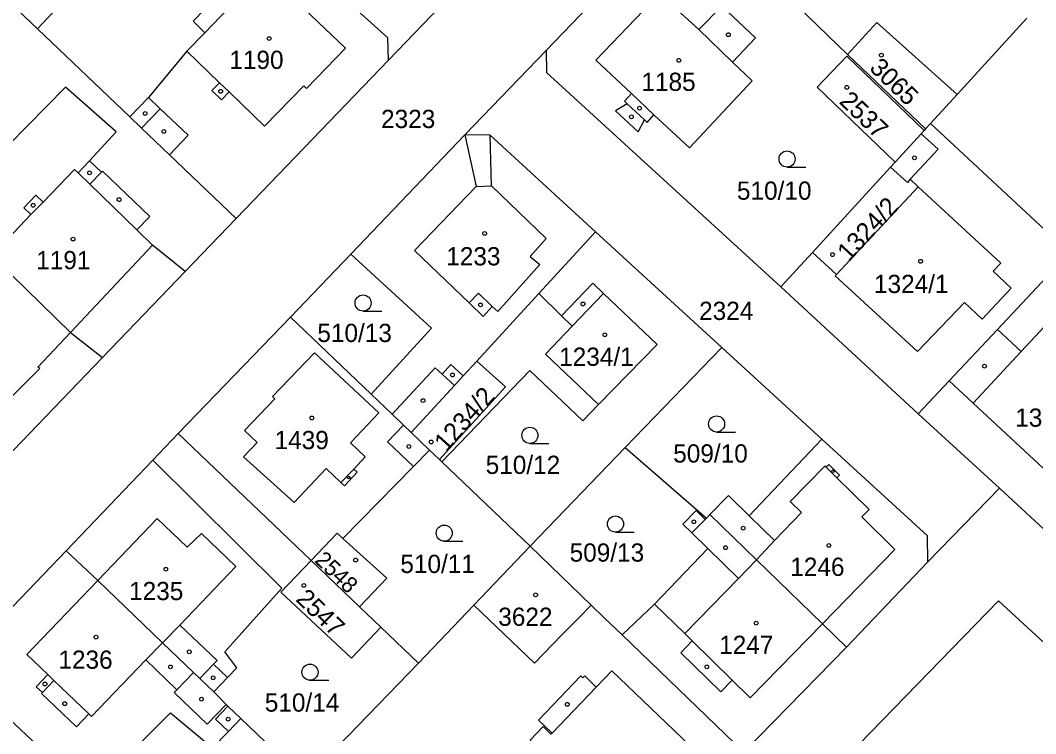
# Model space of a CAD drawing. Extents: x -679220 to -673243, y -1075091 to -1066557.
# Drawn here: x -675883.3 to -675788.6, y -1072056.6 to -1071990 of the extents above; entities that cross this region are included whole.
import ezdxf

# ---------------------------------------------------------------- set-up
doc = ezdxf.new("R2010")
doc.units = 0
for name, color, linetype in [('Hranice parcel', 7, 'Continuous'), ('Parcelní čísla', 7, 'Continuous'), ('Vnitřní kresba', 7, 'Continuous'), ('Značky budov', 7, 'Continuous'), ('Značky kultur', 7, 'Continuous')]:
    doc.layers.add(name, color=color, linetype=linetype)

msp = doc.modelspace()

# ---------------------------------------------------------------- linework, layer by layer
at = {"layer": 'Hranice parcel'}
for p, q in [((-675881.66, -1071990.83), (-675867.2, -1071975.24)), ((-675820.87, -1071978.95), (-675834.25, -1071992.83)), ((-675820.87, -1071978.95), (-675806.12, -1071993.2)), ((-675890.64, -1071982.25), (-675881.66, -1071990.83)), ((-675848.93, -1071993.73), (-675841.54, -1071986.02)), ((-675789.4, -1071989.83), (-675795.92, -1071996.95)), ((-675881.66, -1071990.83), (-675873.06, -1071999.04)), ((-675841.83, -1072000.7), (-675834.25, -1071992.83)), ((-675863.14, -1072008.51), (-675848.93, -1071993.73)), ((-675806.12, -1071993.2), (-675798.85, -1072000.15)), ((-675798.4, -1071999.65), (-675795.92, -1071996.95)), ((-675799, -1072000.3), (-675799.27, -1072000.6)), ((-675798.85, -1072000.15), (-675799, -1072000.3)), ((-675798.4, -1071999.65), (-675798.85, -1072000.15)), ((-675785.46, -1072011.69), (-675798.4, -1071999.65)), ((-675841.83, -1072000.7), (-675852.46, -1072011.83)), ((-675799.27, -1072000.6), (-675801.69, -1072003.25)), ((-675867.89, -1072013.44), (-675863.14, -1072008.51)), ((-675834.92, -1072015.5), (-675829.63, -1072009.75)), ((-675817.86, -1072020.54), (-675829.63, -1072009.75)), ((-675852.46, -1072011.83), (-675858.09, -1072017.72)), ((-675809.41, -1072011.67), (-675812.34, -1072014.87)), ((-675875.62, -1072021.48), (-675867.89, -1072013.44)), ((-675840.71, -1072021.8), (-675834.92, -1072015.5)), ((-675812.34, -1072014.87), (-675799.53, -1072026.71)), ((-675858.09, -1072017.72), (-675868.54, -1072028.55)), ((-675850.57, -1072024.9), (-675858.09, -1072017.72)), ((-675817.86, -1072020.54), (-675826.86, -1072029.88)), ((-675808.52, -1072029.09), (-675817.86, -1072020.54)), ((-675884.7, -1072030.92), (-675875.62, -1072021.48)), ((-675799.53, -1072026.71), (-675791.97, -1072033.67)), ((-675868.54, -1072028.55), (-675870.92, -1072031.05)), ((-675856.15, -1072040.41), (-675868.54, -1072028.55)), ((-675846.83, -1072028.46), (-675845.12, -1072030.1)), ((-675826.86, -1072029.88), (-675835.72, -1072039.08)), ((-675826.86, -1072029.88), (-675819.29, -1072036.44)), ((-675845.12, -1072030.1), (-675844.17, -1072030.98)), ((-675870.92, -1072031.05), (-675878.99, -1072039.49)), ((-675844.17, -1072030.98), (-675843.97, -1072031.2)), ((-675835.72, -1072039.08), (-675843.97, -1072031.2)), ((-675791.97, -1072033.67), (-675798.63, -1072040.54)), ((-675791.97, -1072033.67), (-675786.57, -1072038.64)), ((-675818.97, -1072036.12), (-675819.29, -1072036.44)), ((-675840.97, -1072044.56), (-675835.72, -1072039.08)), ((-675835.72, -1072039.08), (-675830.03, -1072044.56)), ((-675878.99, -1072039.49), (-675889.45, -1072050.36)), ((-675851.64, -1072044.73), (-675856.15, -1072040.41)), ((-675806.24, -1072048.49), (-675798.63, -1072040.54)), ((-675849.65, -1072046.63), (-675851.64, -1072044.73)), ((-675840.97, -1072044.56), (-675846.15, -1072049.98)), ((-675846.15, -1072049.98), (-675849.65, -1072046.63)), ((-675827.14, -1072047.35), (-675815.81, -1072058.29)), ((-675815.81, -1072058.29), (-675806.24, -1072048.49)), ((-675889.45, -1072050.36), (-675878, -1072061.1)), ((-675856.72, -1072060.87), (-675846.15, -1072049.98)), ((-675862.71, -1072055.13), (-675856.72, -1072060.87))]:
    msp.add_line(p, q, dxfattribs=at)
for points in [[(-675858.37, -1071983.2), (-675860.31, -1071985.21), (-675863.53, -1071988.54), (-675864.44, -1071987.66), (-675864.81, -1071988.05), (-675865, -1071987.87), (-675867.17, -1071990.12), (-675866.07, -1071991.18), (-675867.74, -1071992.91), (-675871.32, -1071997.22), (-675873.06, -1071999.04)], [(-675848.93, -1071993.73), (-675849.01, -1071991.65), (-675858.37, -1071983.2)], [(-675826.28, -1071996.85), (-675826.93, -1071997.58), (-675826.68, -1071997.8), (-675827.77, -1071998.48), (-675825.66, -1072000.44), (-675825.06, -1071999.32), (-675824.82, -1071999.54), (-675824.2, -1071998.83), (-675820.87, -1072001.92), (-675815.03, -1071995.66), (-675816.85, -1071993.94), (-675814.7, -1071991.66), (-675817.85, -1071988.7), (-675820, -1071990.89), (-675823.68, -1071987.53), (-675829.61, -1071993.73), (-675826.28, -1071996.85)], [(-675795.92, -1071996.95), (-675803.41, -1071990.22), (-675806.12, -1071993.2)], [(-675834.25, -1071992.83), (-675834.22, -1071994.88), (-675812.34, -1072014.87)], [(-675799, -1072000.3), (-675806.19, -1071993.38), (-675808.95, -1071996.26), (-675801.69, -1072003.25)], [(-675867.89, -1072013.44), (-675870.94, -1072010.99), (-675872.41, -1072009.58), (-675871.2, -1072008.33), (-675875.6, -1072004.09), (-675875.71, -1072004.2), (-675876.81, -1072003.14), (-675874.33, -1072000.43), (-675879.05, -1071996.27), (-675886.17, -1072003.47), (-675888.43, -1072001.12), (-675890.47, -1072003.13), (-675892.63, -1072005.27)], [(-675873.06, -1071999.04), (-675871.96, -1072000.09), (-675869.36, -1072002.57), (-675863.14, -1072008.51)], [(-675829.63, -1072009.75), (-675839.47, -1072000.75), (-675841.83, -1072000.7)], [(-675799.27, -1072000.6), (-675797.69, -1072002.05), (-675800.28, -1072004.85), (-675799.54, -1072005.54), (-675807.16, -1072013.74), (-675809.41, -1072011.67)], [(-675801.69, -1072003.25), (-675802.12, -1072003.71), (-675809.41, -1072011.67)], [(-675892.63, -1072005.27), (-675887.79, -1072010.13), (-675885.95, -1072011.97), (-675885.52, -1072012.38), (-675878.61, -1072019.15), (-675875.62, -1072021.48)], [(-675852.46, -1072011.83), (-675844.93, -1072018.75), (-675850.57, -1072024.9)], [(-675786.65, -1072012.97), (-675792.16, -1072018.85), (-675796.66, -1072023.65), (-675799.53, -1072026.71)], [(-675843.97, -1072031.2), (-675835.75, -1072022.67), (-675830.81, -1072027.37), (-675829.35, -1072025.87), (-675823.89, -1072020.26), (-675828.88, -1072015.5), (-675829.88, -1072014.54), (-675832.82, -1072017.59), (-675834.92, -1072015.5)], [(-675846.83, -1072028.46), (-675842.8, -1072024.08), (-675841.99, -1072023.19), (-675840.71, -1072021.8)], [(-675840.71, -1072021.8), (-675838.04, -1072024.21), (-675844.17, -1072030.98)], [(-675850.57, -1072024.9), (-675848.61, -1072026.77), (-675847.54, -1072027.79), (-675846.83, -1072028.46)], [(-675808.52, -1072029.09), (-675815.3, -1072036.23), (-675817.23, -1072034.34), (-675818.97, -1072036.12)], [(-675798.63, -1072040.54), (-675798.67, -1072038.1), (-675808.52, -1072029.09)], [(-675853.19, -1072038.34), (-675846.6, -1072031.65), (-675845.12, -1072030.1)], [(-675865.22, -1072052.66), (-675863.95, -1072051.33), (-675863.08, -1072050.42), (-675864.21, -1072048.93), (-675858.88, -1072042.99), (-675870.92, -1072031.05)], [(-675819.29, -1072036.44), (-675819.41, -1072036.57), (-675820.26, -1072035.74), (-675821.5, -1072037.01), (-675820.65, -1072037.83), (-675819.16, -1072039.29), (-675824.12, -1072044.48), (-675827.14, -1072047.35)], [(-675818.97, -1072036.12), (-675814.63, -1072040.33), (-675808.47, -1072046.3), (-675806.24, -1072048.49)], [(-675856.15, -1072040.41), (-675853.72, -1072037.86), (-675853.19, -1072038.34)], [(-675851.64, -1072044.73), (-675849.08, -1072042.05), (-675853.19, -1072038.34)], [(-675878.99, -1072039.49), (-675876.06, -1072042.27), (-675870.01, -1072048.07), (-675867.12, -1072050.84), (-675866.53, -1072051.41), (-675865.22, -1072052.66)], [(-675849.65, -1072046.63), (-675852.4, -1072049.5), (-675858.97, -1072043.35), (-675856.15, -1072040.41)], [(-675830.03, -1072044.56), (-675831.19, -1072045.75), (-675832.78, -1072047.34), (-675835.33, -1072049.99), (-675840.97, -1072044.56)], [(-675821.11, -1072113.32), (-675840.72, -1072094.24), (-675792.04, -1072044.17), (-675771.9, -1072062.7)], [(-675827.14, -1072047.35), (-675828.82, -1072045.74), (-675830.03, -1072044.56)], [(-675823.42, -1072061.81), (-675820.11, -1072058.35), (-675828.11, -1072050.7), (-675829.56, -1072052.21), (-675830.64, -1072051.17), (-675830.82, -1072051.35), (-675831.01, -1072051.16), (-675834.96, -1072055.28), (-675833.68, -1072056.5), (-675833.79, -1072056.61), (-675834.53, -1072055.89), (-675835.74, -1072057.15), (-675834.99, -1072057.86), (-675838.36, -1072061.37), (-675834.56, -1072064.99), (-675834.17, -1072064.73), (-675830.03, -1072068.72), (-675826.59, -1072065.18), (-675826.51, -1072065.28), (-675825.7, -1072064.45)], [(-675865.22, -1072052.66), (-675864.08, -1072053.82), (-675863.91, -1072053.98), (-675862.71, -1072055.13)], [(-675876.87, -1072062.17), (-675869.26, -1072054.6), (-675865.34, -1072057.87), (-675863.87, -1072056.34), (-675862.71, -1072055.13)]]:
    msp.add_lwpolyline(points, dxfattribs=at)
at = {"layer": 'Vnitřní kresba'}
for p, q in [((-675866.07, -1071991.18), (-675863.9, -1071988.93)), ((-675856.81, -1071988.95), (-675852.95, -1071992.62)), ((-675820, -1071990.89), (-675816.85, -1071993.94)), ((-675864.69, -1071995.85), (-675867.74, -1071992.91)), ((-675852.95, -1071992.62), (-675856.59, -1071996.39)), ((-675865.4, -1071996.58), (-675864.69, -1071995.85)), ((-675864.51, -1071997.44), (-675865.4, -1071996.58)), ((-675863.8, -1071996.71), (-675864.69, -1071995.85)), ((-675863.8, -1071996.71), (-675864.51, -1071997.44)), ((-675860.49, -1071999.91), (-675863.8, -1071996.71)), ((-675856.85, -1071996.15), (-675860.49, -1071999.91)), ((-675856.59, -1071996.39), (-675856.85, -1071996.15)), ((-675871.32, -1071997.22), (-675870.22, -1071998.27)), ((-675826.28, -1071996.85), (-675824.2, -1071998.83)), ((-675870.22, -1071998.27), (-675871.96, -1072000.09)), ((-675870.22, -1071998.27), (-675867.62, -1072000.75)), ((-675825.06, -1071999.32), (-675826.68, -1071997.8)), ((-675867.62, -1072000.75), (-675869.36, -1072002.57)), ((-675841.83, -1072000.7), (-675840.78, -1072005.51)), ((-675839.34, -1072005.45), (-675839.47, -1072000.75)), ((-675877.88, -1072004.25), (-675876.81, -1072003.14)), ((-675881.15, -1072006.99), (-675878.21, -1072003.93)), ((-675878.21, -1072003.93), (-675877.88, -1072004.25)), ((-675877.88, -1072004.25), (-675876.79, -1072005.31)), ((-675875.71, -1072004.2), (-675876.79, -1072005.31)), ((-675800.55, -1072005.14), (-675802.12, -1072003.71)), ((-675876.79, -1072005.31), (-675872.41, -1072009.58)), ((-675800.28, -1072004.85), (-675800.55, -1072005.14)), ((-675840.78, -1072005.51), (-675846.5, -1072011.49)), ((-675840.78, -1072005.51), (-675839.34, -1072005.45)), ((-675839.34, -1072005.45), (-675834.23, -1072010.38)), ((-675799.54, -1072005.54), (-675791.83, -1072012.66)), ((-675882.95, -1072007.51), (-675881.83, -1072006.34)), ((-675882.28, -1072008.15), (-675881.15, -1072006.99)), ((-675881.83, -1072006.34), (-675881.15, -1072006.99)), ((-675885.95, -1072011.97), (-675882.28, -1072008.15)), ((-675882.28, -1072008.15), (-675882.95, -1072007.51)), ((-675878.61, -1072019.15), (-675870.94, -1072010.99)), ((-675834.23, -1072010.38), (-675835.72, -1072012.05)), ((-675841.43, -1072016.38), (-675846.5, -1072011.49)), ((-675834.84, -1072012.8), (-675838.73, -1072017.19)), ((-675835.72, -1072012.05), (-675834.84, -1072012.8)), ((-675791.83, -1072012.66), (-675792.55, -1072013.43)), ((-675807.16, -1072013.74), (-675807.29, -1072013.87)), ((-675792.55, -1072013.43), (-675790.86, -1072014.99)), ((-675807.29, -1072013.87), (-675799.62, -1072020.91)), ((-675841.43, -1072016.38), (-675840.56, -1072015.48)), ((-675840.56, -1072015.48), (-675839.28, -1072016.7)), ((-675831.81, -1072018.56), (-675828.88, -1072015.5)), ((-675790.86, -1072014.99), (-675793.57, -1072017.91)), ((-675840.12, -1072017.64), (-675841.43, -1072016.38)), ((-675799.62, -1072020.91), (-675795.23, -1072016.33)), ((-675795.23, -1072016.33), (-675793.57, -1072017.91)), ((-675839.28, -1072016.7), (-675840.12, -1072017.64)), ((-675838.73, -1072017.19), (-675839.28, -1072016.7)), ((-675832.82, -1072017.59), (-675831.81, -1072018.56)), ((-675834.3, -1072021.15), (-675831.81, -1072018.56)), ((-675881.63, -1072022.36), (-675878.61, -1072019.15)), ((-675792.16, -1072018.85), (-675789.94, -1072020.91)), ((-675789.94, -1072020.91), (-675787.77, -1072018.57)), ((-675855.83, -1072021.04), (-675859.76, -1072025.11)), ((-675849.84, -1072026.64), (-675855.83, -1072021.04)), ((-675829.35, -1072025.87), (-675834.3, -1072021.15)), ((-675794.41, -1072025.74), (-675789.94, -1072020.91)), ((-675843.95, -1072023.02), (-675843.14, -1072022.13)), ((-675843.14, -1072022.13), (-675841.99, -1072023.19)), ((-675884.88, -1072025.92), (-675881.46, -1072022.51)), ((-675881.46, -1072022.51), (-675881.63, -1072022.36)), ((-675848.61, -1072026.77), (-675844.6, -1072022.42)), ((-675844.6, -1072022.42), (-675843.95, -1072023.02)), ((-675843.95, -1072023.02), (-675842.8, -1072024.08)), ((-675796.66, -1072023.65), (-675794.41, -1072025.74)), ((-675859.54, -1072025.32), (-675859.76, -1072025.11)), ((-675862.36, -1072028.29), (-675859.54, -1072025.32)), ((-675794.41, -1072025.74), (-675787.01, -1072032.6)), ((-675849.84, -1072026.64), (-675852.49, -1072029.43)), ((-675849.03, -1072029.34), (-675847.54, -1072027.79)), ((-675861.2, -1072029.39), (-675862.36, -1072028.29)), ((-675862.47, -1072030.74), (-675861.2, -1072029.39)), ((-675852.49, -1072029.43), (-675851.11, -1072030.74)), ((-675846.6, -1072031.65), (-675849.03, -1072029.34)), ((-675857.75, -1072034.98), (-675862.47, -1072030.74)), ((-675851.11, -1072030.74), (-675852.17, -1072031.87)), ((-675811.48, -1072034.91), (-675808.25, -1072031.6)), ((-675808.14, -1072031.7), (-675808.25, -1072031.6)), ((-675808.14, -1072031.7), (-675807.89, -1072031.45)), ((-675807.12, -1072032.7), (-675808.14, -1072031.7)), ((-675807.89, -1072031.45), (-675806.87, -1072032.45)), ((-675854.76, -1072031.83), (-675857.75, -1072034.98)), ((-675853.38, -1072033.14), (-675854.76, -1072031.83)), ((-675853.38, -1072033.14), (-675852.17, -1072031.87)), ((-675851.85, -1072032.18), (-675853.05, -1072033.45)), ((-675852.17, -1072031.87), (-675851.85, -1072032.18)), ((-675806.87, -1072032.45), (-675807.12, -1072032.7)), ((-675804.12, -1072035.65), (-675807.12, -1072032.7)), ((-675853.05, -1072033.45), (-675853.38, -1072033.14)), ((-675810.43, -1072035.94), (-675811.48, -1072034.91)), ((-675870.52, -1072036.48), (-675876.06, -1072042.27)), ((-675870.52, -1072036.48), (-675867.73, -1072039.15)), ((-675812.94, -1072038.54), (-675815.3, -1072036.23)), ((-675812.94, -1072038.54), (-675810.43, -1072035.94)), ((-675804.8, -1072036.33), (-675804.12, -1072035.65)), ((-675801.72, -1072039.39), (-675804.8, -1072036.33)), ((-675820.65, -1072037.83), (-675819.41, -1072036.57)), ((-675867.73, -1072039.15), (-675866.39, -1072037.88)), ((-675866.39, -1072037.88), (-675863.17, -1072040.95)), ((-675816.3, -1072042.09), (-675819.16, -1072039.29)), ((-675814.63, -1072040.33), (-675812.94, -1072038.54)), ((-675808.47, -1072046.3), (-675801.72, -1072039.39)), ((-675816.3, -1072042.09), (-675814.63, -1072040.33)), ((-675863.17, -1072040.95), (-675868.4, -1072046.42)), ((-675821.32, -1072047.22), (-675816.3, -1072042.09)), ((-675876.06, -1072042.27), (-675882.67, -1072049.18)), ((-675821.32, -1072047.22), (-675824.12, -1072044.48)), ((-675870.01, -1072048.07), (-675868.4, -1072046.42)), ((-675864.93, -1072049.73), (-675868.4, -1072046.42)), ((-675815.22, -1072053.2), (-675808.47, -1072046.3)), ((-675821.69, -1072049), (-675820.62, -1072047.91)), ((-675820.62, -1072047.91), (-675821.32, -1072047.22)), ((-675816.89, -1072051.56), (-675820.62, -1072047.91)), ((-675871.58, -1072049.68), (-675870.01, -1072048.07)), ((-675882.67, -1072049.18), (-675880.71, -1072051.05)), ((-675876.63, -1072054.96), (-675871.58, -1072049.68)), ((-675871.58, -1072049.68), (-675868.68, -1072052.46)), ((-675865.26, -1072050.08), (-675864.93, -1072049.73)), ((-675817.96, -1072052.65), (-675821.69, -1072049)), ((-675866.53, -1072051.41), (-675865.26, -1072050.08)), ((-675863.95, -1072051.33), (-675865.26, -1072050.08)), ((-675880.71, -1072051.05), (-675881.79, -1072052.18)), ((-675881.22, -1072052.72), (-675880.15, -1072051.59)), ((-675880.15, -1072051.59), (-675880.71, -1072051.05)), ((-675876.89, -1072054.7), (-675880.15, -1072051.59)), ((-675868.68, -1072052.46), (-675867.12, -1072050.84)), ((-675816.89, -1072051.56), (-675817.96, -1072052.65)), ((-675815.22, -1072053.2), (-675816.89, -1072051.56)), ((-675881.79, -1072052.18), (-675881.22, -1072052.72)), ((-675868.68, -1072052.46), (-675868.92, -1072052.71)), ((-675833.68, -1072056.5), (-675829.56, -1072052.21)), ((-675881.22, -1072052.72), (-675881.31, -1072052.81)), ((-675881.31, -1072052.81), (-675878.04, -1072055.9)), ((-675868.92, -1072052.71), (-675865.84, -1072055.66)), ((-675865.84, -1072055.66), (-675864.08, -1072053.82)), ((-675863.91, -1072053.98), (-675865.07, -1072055.19)), ((-675878.04, -1072055.9), (-675876.89, -1072054.7)), ((-675876.89, -1072054.7), (-675876.63, -1072054.96)), ((-675865.07, -1072055.19), (-675863.87, -1072056.34))]:
    msp.add_line(p, q, dxfattribs=at)
at = {"layer": 'Značky budov'}
for centre, radius in [((-675860.067, -1071991.729), 0.175), ((-675817.247, -1071991.369), 0.175), ((-675821.857, -1071993.759), 0.175), ((-675802.977, -1071993.279), 0.175), ((-675864.597, -1071996.649), 0.175), ((-675806.197, -1071996.279), 0.175), ((-675871.627, -1071998.709), 0.175), ((-675825.527, -1071998.219), 0.175), ((-675826.287, -1071999.029), 0.175), ((-675869.897, -1072000.389), 0.175), ((-675799.887, -1072002.849), 0.175), ((-675876.817, -1072004.249), 0.175), ((-675882.077, -1072007.279), 0.175), ((-675874.067, -1072006.749), 0.175), ((-675839.977, -1072009.899), 0.175), ((-675878.357, -1072010.429), 0.175), ((-675807.527, -1072011.879), 0.175), ((-675799.317, -1072012.499), 0.175), ((-675840.357, -1072016.569), 0.175), ((-675830.807, -1072016.479), 0.175), ((-675828.767, -1072019.349), 0.175), ((-675793.357, -1072022.279), 0.175), ((-675842.977, -1072023.099), 0.175), ((-675845.717, -1072025.489), 0.175), ((-675856.097, -1072027.109), 0.175), ((-675847.037, -1072029.769), 0.175), ((-675844.957, -1072029.349), 0.175), ((-675852.635, -1072032.669), 0.117), ((-675807.495, -1072032.079), 0.117), ((-675820.457, -1072036.789), 0.175), ((-675815.867, -1072037.389), 0.175), ((-675817.507, -1072039.209), 0.175), ((-675807.867, -1072038.999), 0.175), ((-675852.007, -1072040.359), 0.175), ((-675869.697, -1072041.219), 0.175), ((-675856.827, -1072042.729), 0.175), ((-675835.217, -1072043.609), 0.175), ((-675814.647, -1072046.249), 0.175), ((-675876.217, -1072047.549), 0.175), ((-675867.517, -1072048.919), 0.175), ((-675869.277, -1072050.329), 0.175), ((-675819.247, -1072050.319), 0.175), ((-675865.287, -1072051.339), 0.175), ((-675880.977, -1072051.919), 0.175), ((-675879.137, -1072053.759), 0.175), ((-675866.387, -1072053.339), 0.175), ((-675832.267, -1072053.819), 0.175), ((-675863.887, -1072055.199), 0.175)]:
    msp.add_circle(centre, radius, dxfattribs=at)
at = {"layer": 'Značky kultur'}
for p, q in [((-675811.773, -1072003.71), (-675810.023, -1072003.71)), ((-675851.313, -1072017.14), (-675849.563, -1072017.14)), ((-675818.343, -1072028.42), (-675816.593, -1072028.42)), ((-675835.753, -1072029.48), (-675834.003, -1072029.48)), ((-675827.773, -1072037.75), (-675826.023, -1072037.75)), ((-675843.743, -1072038.6), (-675841.993, -1072038.6)), ((-675856.263, -1072051.57), (-675854.513, -1072051.57))]:
    msp.add_line(p, q, dxfattribs=at)
for centre in [(-675811.773, -1072002.96), (-675851.313, -1072016.39), (-675818.343, -1072027.67), (-675835.753, -1072028.73), (-675827.773, -1072037), (-675843.743, -1072037.85), (-675856.263, -1072050.82)]:
    msp.add_circle(centre, 0.75, dxfattribs=at)

# ---------------------------------------------------------------- texts
at = {"layer": 'Parcelní čísla'}
for s, p in [('1190', (-675863.784, -1071994.56)), ('1185', (-675825.354, -1071996.61)), ('2323', (-675849.634, -1072000.07)), ('510/10', (-675816.447, -1072006.759)), ('1191', (-675881.794, -1072013.239)), ('1233', (-675843.554, -1072012.88)), ('1324/1', (-675803.667, -1072015.46)), ('2324', (-675819.974, -1072017.97)), ('510/13', (-675855.577, -1072020.029)), ('1234/1', (-675833.027, -1072022.249)), ('1323', (-675790.494, -1072027.93)), ('1439', (-675859.564, -1072030.019)), ('509/10', (-675822.387, -1072031.269)), ('510/12', (-675839.877, -1072032.33)), ('509/13', (-675832.047, -1072040.509)), ('510/11', (-675847.837, -1072041.57)), ('1246', (-675811.474, -1072041.84)), ('1235', (-675873.134, -1072044.1)), ('3622', (-675838.704, -1072046.499)), ('1247', (-675818.104, -1072049.12)), ('1236', (-675879.724, -1072050.499)), ('510/14', (-675860.477, -1072054.499))]:
    msp.add_text(s, height=1.7, dxfattribs=at).set_placement(p)
for s, height, rotation, p in [('3065', 1.7, 316, (-675804.179, -1071994.585)), ('2537', 1.7, 316, (-675806.999, -1071997.685)), ('1324/2', 1.7, 47, (-675806.01, -1072012.596)), ('1234/2', 1.7, 48, (-675843.569, -1072030.352)), ('2548', 1.5, 316, (-675855.908, -1072040.476)), ('2547', 1.7, 316, (-675857.679, -1072044.105))]:
    msp.add_text(s, height=height, rotation=rotation, dxfattribs=at).set_placement(p)

doc.saveas('drawing.dxf')
